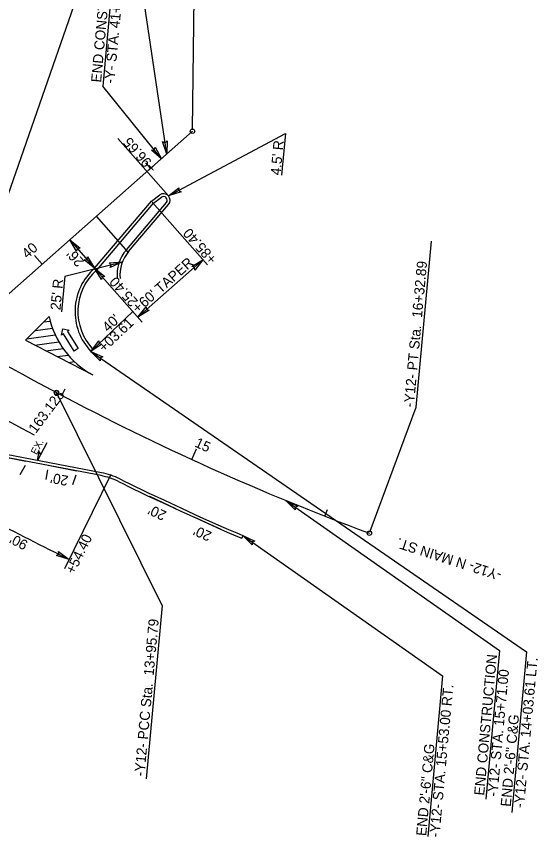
# Model space of a CAD drawing. Extents: x 2010838 to 2015151, y 441905 to 447792.
# Drawn here: x 2012947 to 2013307, y 446720 to 447286 of the extents above; entities that cross this region are included whole.
import ezdxf

# ---------------------------------------------------------------- set-up
doc = ezdxf.new("R2010")
doc.units = 0
for name, color, linetype in [('A-Wall-Abov', 7, 'Continuous'), ('A-Wall-Blow', 7, 'Continuous'), ('A-Wall-Comp', 7, 'Continuous'), ('B-Border', 7, 'Continuous'), ('C-Alignment Geometry', 7, 'Continuous'), ('C-Building', 7, 'Continuous'), ('C-EOP 1', 7, 'Continuous'), ('C-Grave Plots', 7, 'Continuous'), ('C-SHBD-TEXT', 7, 'Continuous'), ('CLRD', 7, 'Continuous'), ('Default_10ft_LIDAR_Contou', 7, 'Continuous'), ('Default_2FT_LIDAR_Contour', 7, 'Continuous'), ('s-Existing Major', 7, 'Continuous'), ('S-Existing Minor', 7, 'Continuous'), ('S-overhead electric', 7, 'Continuous'), ('TEXT-MED', 7, 'Continuous'), ('X2', 7, 'Continuous')]:
    doc.layers.add(name, color=color, linetype=linetype)

msp = doc.modelspace()

# ---------------------------------------------------------------- linework, layer by layer
at = {"layer": 'A-Wall-Abov'}
for p, q in [((2012978.31, 447065.8), (2012979.28, 447070.11)), ((2012979.28, 447070.11), (2012983.66, 447069.12)), ((2012979.59, 447066.59), (2012978.31, 447065.8)), ((2012986.97, 447054.7), (2012979.59, 447066.59)), ((2012983.66, 447069.12), (2012982.39, 447068.33)), ((2012982.39, 447068.33), (2012989.77, 447056.44)), ((2012989.77, 447056.44), (2012986.97, 447054.7))]:
    msp.add_line(p, q, dxfattribs=at)
at = {"layer": 'A-Wall-Blow'}
msp.add_line((2012968.17, 446991.3), (2012961.79, 446979.12), dxfattribs=at)
at = {"layer": 'A-Wall-Comp'}
msp.add_lwpolyline([(2012961.79, 446979.12), (2012962.8, 446985.36), (2012963.93, 446983.22)], close=True, dxfattribs=at)
at = {"layer": 'B-Border'}
msp.add_arc((2014537.56, 449965.84), 3362.24, 239.35482, 242.0055, dxfattribs=at)
at = {"layer": 'C-Alignment Geometry'}
for p, q in [((2012953.45, 447062.14), (2012969.76, 447078.5)), ((2012966.13, 447074.86), (2012970.5, 447075.47)), ((2012960.3, 447069.01), (2012972.02, 447070.63)), ((2012954.46, 447063.16), (2012973.99, 447065.85)), ((2012953.45, 447062.14), (2012999.91, 447038.3)), ((2012959.85, 447058.85), (2012976.43, 447061.14)), ((2012967.6, 447054.88), (2012979.4, 447056.51)), ((2012975.35, 447050.9), (2012982.95, 447051.95)), ((2012983.11, 447046.92), (2012987.21, 447047.49)), ((2012990.86, 447042.95), (2012992.35, 447043.15)), ((2012998.61, 447038.97), (2012998.69, 447038.98))]:
    msp.add_line(p, q, dxfattribs=at)
msp.add_arc((2013028.42, 447091.09), 60, 192.1112, 241.6233, dxfattribs=at)
at = {"layer": 'C-Building'}
for p, q in [((2013039.89, 447180.83), (2013036.58, 447184.58)), ((2012978.58, 447024.18), (2012980.92, 447028.6)), ((2013160.26, 446940.79), (2013162.08, 446945.45))]:
    msp.add_line(p, q, dxfattribs=at)
at = {"layer": 'C-EOP 1'}
for p, q in [((2012964.93, 447114.64), (2012959.64, 447120.63)), ((2013068.25, 446979.94), (2013071.59, 446987.22))]:
    msp.add_line(p, q, dxfattribs=at)
at = {"layer": 'C-SHBD-TEXT'}
msp.add_line((2013024.3, 447122.95), (2013002.41, 447147.73), dxfattribs=at)
at = {"layer": 'CLRD'}
msp.add_line((2012827.44, 446993.23), (2013068.81, 447206.37), dxfattribs=at)
for centre, radius, start, end in [((2014537.56, 449965.84), 3329.24, 237.13174, 242.0055), ((2014537.56, 449965.84), 3329.24, 237.13174, 242.0055), ((2013813.97, 448604.66), 1787.68, 242.0055, 249.60464), ((2013813.97, 448604.66), 1787.68, 242.0055, 249.60464)]:
    msp.add_arc(centre, radius, start, end, dxfattribs=at)
at = {"layer": 'Default_10ft_LIDAR_Contou'}
for p, q in [((2012906.83, 447063.34), (2013011.33, 447363.33)), ((2013051.02, 447190.65), (2013029.62, 447335.79)), ((2013068.83, 447207.87), (2013070.35, 447328.74)), ((2013223.32, 447016.04), (2013233.85, 447130.56)), ((2013047.77, 446879.07), (2012974.86, 447026.15)), ((2013191.5, 446930.46), (2013223.32, 447016.04)), ((2013047.77, 446879.07), (2013036.78, 446759.57))]:
    msp.add_line(p, q, dxfattribs=at)
for centre in [(2013068.81, 447206.37), (2013068.81, 447206.37), (2012974.86, 447026.15), (2013190.97, 446929.05)]:
    msp.add_circle(centre, 1.5, dxfattribs=at)
at = {"layer": 's-Existing Major'}
for points in [[(2013051.24, 447199.78), (2013051.02, 447190.65), (2013048.12, 447199.37), (2013049.87, 447198.47)], [(2013042.92, 447195.41), (2013047.39, 447187.45), (2013040.45, 447193.47), (2013042.41, 447193.58)], [(2013060.89, 447164.66), (2013052.22, 447161.8), (2013059.46, 447167.46), (2013059.19, 447165.51)], [(2012988.77, 447123.68), (2012983.97, 447131.45), (2012991.16, 447125.72), (2012989.2, 447125.53)], [(2012996.39, 447119.73), (2013001.18, 447111.96), (2012993.99, 447117.68), (2012995.95, 447117.88)], [(2013011.3, 447115.58), (2013020.41, 447116.24), (2013012.01, 447112.51), (2013012.74, 447114.34)], [(2013068.29, 447113.01), (2013076.06, 447117.8), (2013070.34, 447110.61), (2013070.14, 447112.58)], [(2013005.98, 447104.19), (2013001.18, 447111.96), (2013008.37, 447106.24), (2013006.41, 447106.04)], [(2013038.86, 447082.89), (2013031.09, 447078.09), (2013036.81, 447085.28), (2013037.01, 447083.32)], [(2013006.21, 447059.54), (2012998.6, 447054.48), (2013004.08, 447061.87), (2013004.34, 447059.91)], [(2013005.14, 447048.1), (2012998.6, 447054.48), (2013006.96, 447050.67), (2013005.11, 447050)], [(2013139.83, 446945.18), (2013133.35, 446951.62), (2013141.68, 446947.73), (2013139.82, 446947.08)], [(2013110.09, 446921.11), (2013103.61, 446927.55), (2013111.94, 446923.66), (2013110.08, 446923.01)], [(2012976.28, 446916.37), (2012983.68, 446911.01), (2012974.85, 446913.56), (2012976.59, 446914.49)]]:
    msp.add_lwpolyline(points, close=True, dxfattribs=at)
at = {"layer": 'S-Existing Minor'}
for p, q in [((2013016.29, 447340.2), (2013006.85, 447237.48)), ((2013047.39, 447187.45), (2013006.85, 447237.48)), ((2013017.15, 447201.51), (2013052.22, 447161.8)), ((2013052.22, 447161.8), (2013133.02, 447204.81)), ((2013133.02, 447204.81), (2013130.37, 447176.04)), ((2013041.03, 447157.48), (2013079.22, 447114.23)), ((2012983.97, 447131.45), (2013001.18, 447111.96)), ((2012980.63, 447106.37), (2013020.41, 447116.24)), ((2013031.09, 447078.09), (2013076.06, 447117.8)), ((2013001.18, 447111.96), (2013034.02, 447074.77)), ((2012980.63, 447106.37), (2012978.39, 447081.91)), ((2012998.6, 447054.48), (2013027.66, 447081.98)), ((2012998.6, 447054.48), (2013299.58, 446847.19)), ((2013012.36, 446969.51), (2012980.5, 446904.53)), ((2013133.35, 446951.62), (2013280.89, 446848.16)), ((2013103.61, 446927.55), (2013241.55, 446830.71)), ((2013280.89, 446848.16), (2013271.45, 446745.43)), ((2013299.58, 446847.19), (2013289.38, 446736.32)), ((2013241.55, 446830.71), (2013231.36, 446719.85))]:
    msp.add_line(p, q, dxfattribs=at)
msp.add_arc((2013813.97, 448604.66), 1886.22, 242.0055, 243.88408, dxfattribs=at)
at = {"layer": 'S-overhead electric'}
for p, q in [((2013040.42, 447158.17), (2013046.19, 447162.46)), ((2013001.18, 447111.96), (2013040.42, 447158.17)), ((2013024.66, 447123.39), (2013052.28, 447155.91)), ((2013006.01, 446970.72), (2012918.08, 446987.42)), ((2012953.21, 446975.66), (2012949.63, 446969.27)), ((2012968.56, 446972.74), (2012967.48, 446966.15)), ((2012988.21, 446969.01), (2012985.93, 446962.31)), ((2013018.58, 446966.54), (2013022.09, 446964.83))]:
    msp.add_line(p, q, dxfattribs=at)
msp.add_lwpolyline([(2013022.08, 446964.82), (2013024.52, 446963.63), (2013038.25, 446956.96), (2013049.36, 446951.73), (2013061.18, 446946.23), (2013074.45, 446940.22), (2013086.36, 446934.84), (2013093.6, 446931.67), (2013099.55, 446929.19), (2013103.61, 446927.55)], dxfattribs=at)
for centre, radius, start, end in [((2013048.85, 447158.82), 4.5, 319.6617, 126.1358), ((2013043.72, 447107.21), 25, 139.6617, 185.4644), ((2013027.66, 447081.98), 40, 131.4451, 223.4194), ((2012996.67, 446921.6), 50, 64.0197, 79.2418)]:
    msp.add_arc(centre, radius, start, end, dxfattribs=at)
at = {"layer": 'TEXT-MED'}
for p, q in [((2013041.8, 447156.7), (2013047.37, 447160.84)), ((2013002.71, 447110.67), (2013041.8, 447156.7)), ((2013023.14, 447124.68), (2013050.75, 447157.2)), ((2013005.63, 446968.75), (2012917.7, 446985.46)), ((2013017.7, 446964.75), (2013021.22, 446963.04)), ((2013103.61, 446927.55), (2013102.83, 446925.71))]:
    msp.add_line(p, q, dxfattribs=at)
msp.add_lwpolyline([(2013021.21, 446963.02), (2013023.65, 446961.83), (2013037.38, 446955.15), (2013048.51, 446949.92), (2013060.35, 446944.41), (2013073.62, 446938.4), (2013085.54, 446933.01), (2013092.82, 446929.83), (2013098.79, 446927.34), (2013102.83, 446925.71)], dxfattribs=at)
for centre, radius, start, end in [((2013048.85, 447158.82), 2.5, 319.6617, 126.1358), ((2013043.72, 447107.21), 27, 139.6617, 185.4644), ((2013027.66, 447081.98), 38, 131.4451, 223.4194), ((2012996.67, 446921.6), 48, 64.0197, 79.2418)]:
    msp.add_arc(centre, radius, start, end, dxfattribs=at)
at = {"layer": 'X2'}
for p, q in [((2012953.77, 446978.61), (2012928.23, 446983.46)), ((2012988.77, 446971.96), (2012969.12, 446975.69)), ((2013057.4, 446945.79), (2013039.29, 446954.28)), ((2013088.65, 446931.69), (2013070.4, 446939.87))]:
    msp.add_line(p, q, dxfattribs=at)

# ---------------------------------------------------------------- texts
at = {"layer": 'A-Wall-Blow'}
msp.add_text('EX.', height=5, rotation=62.3343, dxfattribs=at).set_placement((2012961.19, 446982.78))
at = {"layer": 'C-Grave Plots'}
for s, rotation, p in [('+96.65', 131.4451, (2013044.72, 447181.29)), ("4.5' R", 84.7467, (2013129.63, 447175.78)), ('+85.40', 131.4451, (2013086.05, 447118.54)), ("26'", 131.4451, (2012994.55, 447116.68)), ("60' TAPER", 41.4451, (2013035.65, 447084.33)), ("25' R", 84.7467, (2012977.58, 447082.77)), ('+25.40', 131.4451, (2013035.19, 447085.06)), ('+03.61', 43.4194, (2013007.78, 447053.49)), ("40'", 43.4194, (2013010.52, 447067.39)), ("20'", 169.2418, (2012983.46, 446968.46)), ("20'", 154.905, (2013051.39, 446943.72)), ("90' TAPER", 152.5297, (2012955.77, 446923.26)), ('+54.40', 63.8841, (2012987.04, 446900.22)), ("20'", 155.8405, (2013082.67, 446929.52)), ('-Y12- N MAIN ST.', 162.1906, (2013282.93, 446902.86))]:
    msp.add_text(s, height=7, rotation=rotation, dxfattribs=at).set_placement(p)
at = {"layer": 'C-SHBD-TEXT'}
msp.add_text('163.128', height=7, rotation=53.189, dxfattribs=at).set_placement((2012960.55, 446997.46))
at = {"layer": 'Default_10ft_LIDAR_Contou'}
for s, p in [('-Y12- PT Sta.  16+32.89', (2013221.67, 447015.79)), ('-Y12- PCC Sta.  13+95.79', (2013035.58, 446761.05))]:
    msp.add_text(s, height=7, rotation=84.7467, dxfattribs=at).set_placement(p)
at = {"layer": 'Default_2FT_LIDAR_Contour'}
for s, rotation, p in [('40', 41.4451, (2012954.72, 447118.13)), ('15', 335.3456, (2013069.83, 446989))]:
    msp.add_text(s, height=7, rotation=rotation, dxfattribs=at).set_placement(p)
at = {"layer": 'S-Existing Minor'}
for s, p in [('END CONSTRUCTION', (2013005.66, 447239.87)), ('-Y- STA. 41+10.00', (2013014.8, 447239.03)), ('END CONSTRUCTION', (2013270.27, 446747.83)), ('-Y12- STA. 14+03.61 LT.', (2013297.74, 446739.24)), ('-Y12- STA. 15+71.00', (2013279.41, 446746.99)), ('-Y12- STA. 15+53.00 RT.', (2013239.37, 446719.06)), ('END 2\'-6" C&G', (2013288.6, 446740.08)), ('END 2\'-6" C&G', (2013230.23, 446719.9))]:
    msp.add_text(s, height=7, rotation=84.7467, dxfattribs=at).set_placement(p)

doc.saveas('drawing.dxf')
